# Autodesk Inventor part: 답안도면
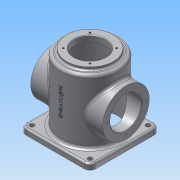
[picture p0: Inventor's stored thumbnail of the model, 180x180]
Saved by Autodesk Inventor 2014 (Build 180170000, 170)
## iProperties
Created: 2015-10
Part Number: 답안도면
Material: 알루미늄 6061
Document SubType Name: Modeling
Designer: net
Density: 2.71 g/cm^3
Appearance: 알루미늄 - 평지
Mass: 954.135 g
Surface Area: 1042.2 cm^2
Volume: 352.079 cm^3
Author: net
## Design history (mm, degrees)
sketch "스케치1"
  geometry: 1 further point
sketch "스케치2"
  geometry: L1 (60, 60)-(-60, 60); L2 (-60, 60)-(-60, -60); L3 (-60, -60)-(60, -60); L4 (60, -60)-(60, 60); L5 (60, 60)-(-60, -60); L6 (-60, 60)-(60, -60); 1 further point
  constraints: 12 end point, 2 midpoint, 2 parallel, 1 horizontal, 1 perpendicular
  dimensions: "d0" = 120 distance of L3.end L2.end; "d1" = 120 distance between parallel lines of L3 L1
extrude "돌출1" new body sketch "스케치2" distance "d2" = 10; taper "d3" = 0 deg
sketch "스케치4"
  geometry: L1 (-60, 0)-(60, 0) reference; L2 (-60, 0)-(-60, 10) reference; L3 (60, 0)-(60, 10) reference; L4 (-60, 10)-(60, 10) reference; L5 (0, 0)-(0, 120); L6 (0, 120)-(-50, 120); L7 (-50, 120)-(-50, 0); L8 (-45, 0)-(-45, 115); L9 (-45, 115)-(0, 115); L10 (-45, 0)-(0, 0); 1 further point
  constraints: 12 end point, 3 point on line, 2 horizontal, 2 midpoint, 1 parallel, 1 vertical
  dimensions: "d10" = 50 distance between parallel lines of L5 L7; "d11" = 5 distance between parallel lines of L8 L7; "d16" = 120 distance between parallel lines of L1 L6; "d17" = 5 distance between parallel lines of L9 L6; "d18" = 10 distance from line of L8.start L4
revolve "회전2" stored, may be unused: angle "d19" = 90 deg
revolve "회전3" stored, may be unused: angle "d20" = 90 deg
sketch "스케치5"
  geometry: C1 r 40 at (0, 0); C2 r 27 at (0, 0); C3 r 50 at (0, 0) reference; C4 r 27 at (0, 0); 1 further point
  constraints: 3 centre point, 3 coincident, 1 concentric
  dimensions: "d21" = 80 diameter of C1; "d22" = 54 diameter of C2
extrude "돌출2" join sketch "스케치5" distance "d23" = 5; taper "d24" = 0 deg
node "작업 평면2"
sketch "스케치8"
  geometry: L1 (50, 120)-(-50, 120) reference; L2 (-50, 10)-(50, 10) reference; L3 (-60, 0)-(60, 0) reference; L4 (-60, 0)-(60, 0) reference; L5 (60, 0)-(60, 10) reference; L6 (-60, 10)-(60, 10) reference; L7 (-60, 0)-(-60, 10) reference; C1 r 40 at (0, 60); C2 r 27 at (0, 60); 2 further points
  constraints: 2 centre point, 1 coincident, 1 midpoint, 1 vertical alignment
  dimensions: "d51" = 80 diameter of C1; "d52" = 54 diameter of C2; "d53" = 60 distance of point (0, 0) C1.centre
  node "투영된 루프3"
  node "투영된 루프4"
extrude "돌출6" join sketch "스케치8" stored distance "d54" = 5; taper "d55" = 0 deg
extrude "돌출7" cut sketch "스케치8" stored distance "d56" = 5; taper "d57" = 0 deg
sketch "스케치9"
  geometry: C1 r 27 at (0, 0) reference; C2 r 27 at (0, 0)
  constraints: 1 centre point, 1 coincident
  dimensions: "d58" = 54 diameter of C2
extrude "돌출8" cut sketch "스케치9" stored distance "d59" = 5; taper "d60" = 0 deg
sketch "스케치10"
  geometry: C1 r 27 at (0, 0) reference; 2 further points
  constraints: 1 horizontal alignment
  dimensions: "d61" = 45 deg dimension on C1.centre point (22.981, -22.981) point (33.702, 0); "d62" = 32.5 distance of C1.centre point (22.981, -22.981)
hole "구멍2" sketch "스케치10" at (22.981, -22.981) diameter "d63" = 3.242; stored, may be unused: countersink angle "d67" = 90 deg, drill point angle "d69" = 118 deg; dims "d64" = 8, "d65" = 4, "d66" = 2, "d68" = 10
sketch "스케치11"
  geometry: C1 r 27 at (0, 0) reference; 2 further points
  constraints: 1 horizontal alignment
  dimensions: "d73" = 32.5 distance of C1.centre point (-32.5, 0)
hole "구멍3" sketch "스케치11" at (-32.5, 0) diameter "d74" = 3.242; stored, may be unused: countersink angle "d78" = 90 deg, drill point angle "d80" = 118 deg; dims "d75" = 8, "d76" = 4, "d77" = 2, "d79" = 10
hole "구멍4" diameter "d86" = 8; stored, may be unused: countersink angle "d90" = 90 deg, drill point angle "d92" = 0 deg; dims "d84" = 10, "d85" = 10, "d87" = 8, "d88" = 4, "d89" = 2, "d91" = 10
fillet "모깎기1" dims "d99" = 10
fillet "모깎기2" dims "d100" = 5
fillet "모깎기3" dims "d101" = 5
fillet "모깎기4" dims "d102" = 5
fillet "모깎기5" dims "d103" = 5
fillet "모깎기6" dims "d104" = 3
fillet "모깎기7" dims "d105" = 3
chamfer "모따기1" distance "d106" = 3; stored, may be unused: second distance "d107" = 2, angle "d108" = 45 deg
chamfer "모따기2" distance "d109" = 1; stored, may be unused: second distance "d110" = 2, angle "d111" = 45 deg
chamfer "모따기3" distance "d112" = 1; stored, may be unused: second distance "d113" = 2, angle "d114" = 45 deg
node "작업 평면3"
sketch "스케치12"
  geometry: L1 (-48, -60)-(48, -60) reference; L2 (-62, 40)-(-62, -40) reference; L3 (-50, -60)-(50, -60) reference; 3 further points
  constraints: 1 midpoint, 1 vertical alignment, 1 other
  dimensions: "d117" = 70 distance from line of L1 point (0, 10)
feature "엠보싱1" sketch "스케치12" dims "d0" = 120, "d1" = 120, "d115" = 0.5, "d116" = 0
node "작업 평면1"
sketch "스케치6"
  geometry: L1 (50, 120)-(-50, 120) reference; L2 (-50, 10)-(50, 10) reference; C1 r 40 at (0, 60); C2 r 27 at (0, 60); 1 further point
  constraints: 2 centre point, 1 coincident, 1 vertical alignment
  dimensions: "d26" = 80 diameter of C1; "d27" = 54 diameter of C2; "d28" = 60 distance of point (0, 0) C1.centre
  node "투영된 루프2"
extrude "돌출3" join sketch "스케치6" stored distance "d29" = 5; taper "d30" = 0 deg
extrude "돌출4" cut sketch "스케치6" stored distance "d31" = 5; taper "d32" = 0 deg
extrude "돌출5" cut sketch "스케치5" stored distance "d33" = 5; taper "d34" = 0 deg
hole "구멍1" diameter "d37" = 8; stored, may be unused: countersink angle "d41" = 90 deg, drill point angle "d43" = 0 deg; dims "d35" = 10, "d36" = 10, "d38" = 6, "d39" = 4, "d40" = 2, "d42" = 8
sketch "스케치7"
  geometry: C1 r 27 at (0, 0) reference; C2 r 40 at (0, 0) reference
node "솔리드1"
mirror "대칭4"
pattern_circular "원형 패턴1" dims angle "d71" = 360 deg
pattern_circular "원형 패턴2" dims angle "d82" = 360 deg
mirror "대칭5"
pattern_linear "직사각형 패턴2" dims "d95" = 100
mirror "대칭3"
pattern_linear "직사각형 패턴1" dims "d46" = 100
mirror "대칭1"
mirror "대칭2"
other parameters: "d25" = 62.5, "d50" = 62
